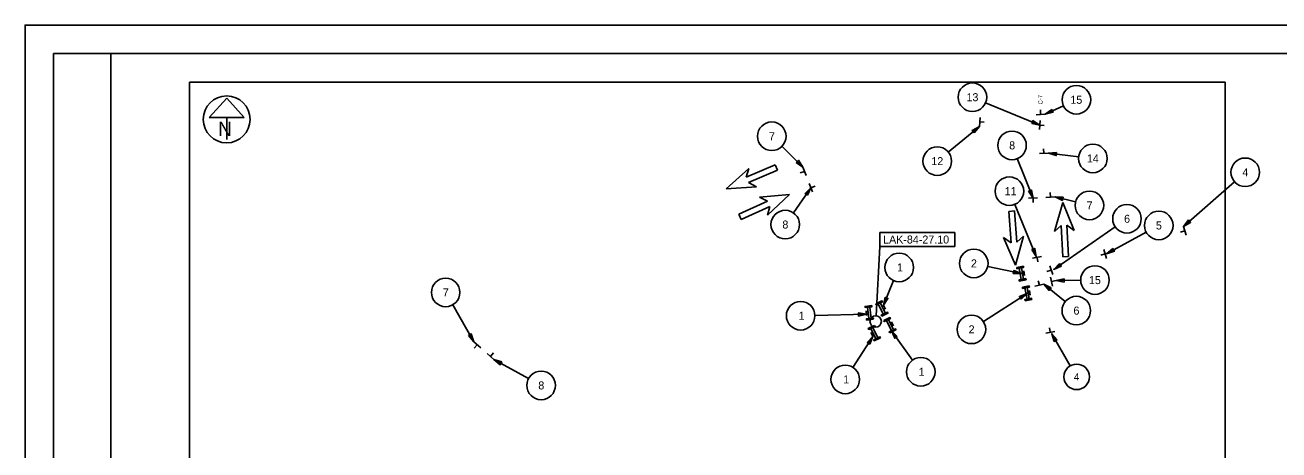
# Model space of a CAD drawing. Extents: x 0 to 54.8, y 0 to 22.
# Drawn here: x 0 to 21.94, y 14.57 to 22 of the extents above; entities that cross this region are included whole.
import ezdxf

# ---------------------------------------------------------------- set-up
doc = ezdxf.new("R2010")
doc.units = 0
for name, color, linetype in [('GM_P_County_Alignment', 7, 'Continuous'), ('GM_X_County', 7, 'Continuous'), ('GM_X_Minor_Lake', 7, 'Continuous'), ('GM_X_Minor_Lake_Text', 7, 'Continuous'), ('GM_X_Minor_River_Text', 7, 'Continuous'), ('GM_X_Township', 7, 'Continuous'), ('GM_X_Township_Road', 7, 'Continuous'), ('GM_X_Township_Road_Text', 7, 'Continuous')]:
    doc.layers.add(name, color=color, linetype=linetype)

msp = doc.modelspace()

# ---------------------------------------------------------------- linework, layer by layer
at = {"layer": 'GM_X_County'}
msp.add_lwpolyline([(0, 0), (34, 0), (34, 22), (0, 22)], close=True, dxfattribs=at)
at = {"layer": 'GM_X_Minor_Lake'}
for p, q in [((3.528, 20.724), (3.22, 20.383)), ((3.836, 20.383), (3.528, 20.724)), ((3.22, 20.383), (3.836, 20.383)), ((3.528, 20.383), (3.528, 19.996)), ((14.891, 16.914), (14.96, 18.128))]:
    msp.add_line(p, q, dxfattribs=at)
for points in [[(21, 21), (21, 11.75), (15, 11.75), (15, 8.743), (2.878, 8.743), (2.878, 21)], [(14.96, 18.368), (14.96, 18.128), (16.268, 18.128), (16.268, 18.368)]]:
    msp.add_lwpolyline(points, close=True, dxfattribs=at)
for centre, radius in [((3.528, 20.35), 0.41), ((14.885, 16.815), 0.1)]:
    msp.add_circle(centre, radius, dxfattribs=at)
at = {"layer": 'GM_X_Minor_Lake_Text'}
for p, q in [((12.619, 19.339), (13.125, 19.552)), ((13.125, 19.552), (13.164, 19.46)), ((12.269, 19.137), (12.663, 19.491)), ((12.663, 19.491), (12.619, 19.339)), ((13.164, 19.46), (12.657, 19.246)), ((13.145, 19.506), (13.145, 19.506)), ((12.798, 19.171), (12.269, 19.137)), ((12.269, 19.137), (12.269, 19.137)), ((12.657, 19.246), (12.798, 19.171)), ((12.492, 18.692), (12.994, 18.917)), ((12.852, 18.989), (13.379, 19.035)), ((12.994, 18.917), (12.852, 18.989)), ((13.379, 19.035), (12.994, 18.672)), ((13.379, 19.035), (13.379, 19.035)), ((18.012, 18.386), (18.16, 18.894)), ((18.16, 18.894), (18.16, 18.894)), ((18.16, 18.894), (18.359, 18.403)), ((12.533, 18.601), (12.492, 18.692)), ((13.035, 18.826), (12.533, 18.601)), ((12.994, 18.672), (13.035, 18.826)), ((17.214, 18.741), (17.314, 18.748)), ((17.254, 18.192), (17.214, 18.741)), ((17.264, 18.744), (17.264, 18.744)), ((17.314, 18.748), (17.354, 18.2)), ((12.512, 18.646), (12.512, 18.646)), ((18.13, 18.492), (18.012, 18.386)), ((18.158, 17.943), (18.13, 18.492)), ((18.359, 18.403), (18.23, 18.497)), ((18.23, 18.497), (18.258, 17.948)), ((17.333, 17.797), (17.124, 18.283)), ((17.124, 18.283), (17.254, 18.192)), ((17.47, 18.308), (17.333, 17.797)), ((17.354, 18.2), (17.47, 18.308)), ((17.333, 17.797), (17.333, 17.797)), ((18.258, 17.948), (18.158, 17.943)), ((18.208, 17.945), (18.208, 17.945)), ((17.433, 17.549), (17.395, 17.745)), ((17.434, 17.651), (17.434, 17.651)), ((17.473, 17.556), (17.435, 17.753)), ((17.45, 17.674), (17.479, 17.68)), ((17.457, 17.635), (17.487, 17.641)), ((17.475, 17.699), (17.491, 17.621)), ((17.533, 17.204), (17.495, 17.4)), ((17.573, 17.211), (17.535, 17.408)), ((17.55, 17.329), (17.579, 17.335)), ((17.576, 17.354), (17.591, 17.276)), ((15.018, 16.942), (14.93, 17.122)), ((15.054, 16.96), (14.966, 17.14)), ((17.534, 17.306), (17.534, 17.306)), ((17.558, 17.29), (17.587, 17.295)), ((14.727, 16.92), (14.718, 16.999)), ((14.75, 16.983), (14.72, 16.98)), ((14.755, 16.943), (14.725, 16.94)), ((14.741, 17.062), (14.764, 16.864)), ((14.772, 16.965), (14.772, 16.965)), ((14.781, 17.067), (14.804, 16.868)), ((14.992, 17.041), (14.992, 17.041)), ((15.001, 17.068), (15.028, 17.081)), ((15.019, 17.032), (15.046, 17.045)), ((15.02, 17.099), (15.054, 17.027)), ((14.801, 16.691), (14.888, 16.511)), ((14.837, 16.708), (14.924, 16.528)), ((15.159, 16.651), (15.072, 16.831)), ((15.195, 16.668), (15.108, 16.848)), ((15.133, 16.749), (15.133, 16.749)), ((15.143, 16.776), (15.17, 16.789)), ((15.16, 16.74), (15.187, 16.753)), ((15.161, 16.807), (15.196, 16.735)), ((14.835, 16.552), (14.8, 16.624)), ((14.836, 16.619), (14.809, 16.606)), ((14.853, 16.583), (14.826, 16.57)), ((14.863, 16.61), (14.863, 16.61))]:
    msp.add_line(p, q, dxfattribs=at)
for points in [[(17.352, 17.757), (17.47, 17.78), (17.474, 17.76), (17.356, 17.737)], [(17.398, 17.521), (17.516, 17.544), (17.512, 17.564), (17.394, 17.541)], [(17.452, 17.412), (17.57, 17.435), (17.574, 17.415), (17.456, 17.392)], [(14.886, 17.123), (14.994, 17.175), (15.002, 17.157), (14.894, 17.105)], [(17.498, 17.176), (17.616, 17.199), (17.612, 17.219), (17.494, 17.196)], [(14.818, 17.092), (14.699, 17.078), (14.701, 17.058), (14.82, 17.072)], [(14.99, 16.907), (15.098, 16.959), (15.09, 16.977), (14.982, 16.925)], [(14.846, 16.853), (14.727, 16.839), (14.724, 16.859), (14.843, 16.873)], [(14.864, 16.744), (14.756, 16.692), (14.765, 16.674), (14.873, 16.726)], [(15.027, 16.831), (15.135, 16.883), (15.144, 16.865), (15.036, 16.813)], [(15.132, 16.615), (15.24, 16.668), (15.231, 16.686), (15.123, 16.633)], [(14.969, 16.528), (14.861, 16.476), (14.852, 16.494), (14.96, 16.546)]]:
    msp.add_lwpolyline(points, close=True, dxfattribs=at)
at = {"layer": 'GM_X_Minor_River_Text'}
for p, q in [((17.851, 20.44), (17.691, 20.431)), ((17.771, 20.436), (17.767, 20.516)), ((16.699, 20.225), (16.711, 20.385)), ((16.705, 20.305), (16.785, 20.299)), ((17.75, 20.171), (17.761, 20.331)), ((17.755, 20.251), (17.835, 20.245)), ((17.908, 19.761), (17.749, 19.752)), ((17.829, 19.757), (17.824, 19.836)), ((13.64, 19.441), (13.566, 19.412)), ((13.612, 19.516), (13.669, 19.367)), ((13.781, 19.08), (13.723, 19.229)), ((13.752, 19.154), (13.826, 19.183)), ((17.558, 18.969), (17.718, 18.977)), ((17.638, 18.973), (17.642, 18.893)), ((18.025, 18.994), (17.865, 18.985)), ((17.945, 18.989), (17.941, 19.069)), ((20.27, 18.477), (20.317, 18.324)), ((20.294, 18.4), (20.217, 18.377)), ((18.901, 17.995), (18.825, 17.972)), ((18.878, 18.071), (18.925, 17.918)), ((17.631, 17.919), (17.789, 17.95)), ((17.71, 17.935), (17.725, 17.856)), ((17.935, 17.789), (17.982, 17.636)), ((17.958, 17.712), (17.882, 17.689)), ((17.981, 17.433), (17.946, 17.589)), ((17.828, 17.468), (17.672, 17.431)), ((17.75, 17.45), (17.731, 17.527)), ((17.964, 17.511), (18.042, 17.529)), ((17.939, 16.625), (17.925, 16.704)), ((7.854, 16.46), (7.974, 16.354)), ((18.018, 16.64), (17.861, 16.611)), ((7.914, 16.407), (7.861, 16.347)), ((8.205, 16.151), (8.085, 16.256)), ((8.145, 16.203), (8.198, 16.264))]:
    msp.add_line(p, q, dxfattribs=at)
at = {"layer": 'GM_X_Township'}
for points in [[(0.5, 21.5), (1.5, 21.5), (1.5, 0.5), (0.5, 0.5)], [(1.5, 21.5), (33.5, 21.5), (33.5, 0.5), (1.5, 0.5)]]:
    msp.add_lwpolyline(points, close=True, dxfattribs=at)
at = {"layer": 'GM_X_Township_Road'}
for p, q in [((16.809, 20.642), (17.755, 20.251)), ((18.17, 20.588), (17.851, 20.44)), ((16.155, 19.777), (16.699, 20.225)), ((13.245, 19.879), (13.612, 19.516)), ((18.437, 19.696), (17.908, 19.761)), ((17.363, 19.663), (17.638, 18.973)), ((13.445, 18.715), (13.752, 19.154)), ((21.163, 19.259), (20.27, 18.477)), ((18.383, 18.905), (18.025, 18.994)), ((17.32, 18.863), (17.696, 17.953)), ((19.076, 18.469), (18.001, 17.725)), ((19.619, 18.375), (18.925, 18)), ((16.846, 17.778), (17.434, 17.651)), ((15.199, 17.529), (15.02, 17.099)), ((18.203, 17.162), (17.828, 17.468)), ((18.472, 17.535), (18.042, 17.529)), ((16.771, 16.811), (17.534, 17.306)), ((7.484, 17.105), (7.854, 16.46)), ((13.822, 16.919), (14.725, 16.94)), ((14.487, 16.01), (14.835, 16.552)), ((15.528, 16.136), (15.159, 16.651)), ((18.29, 16.038), (17.965, 16.599)), ((8.812, 15.816), (8.205, 16.151))]:
    msp.add_line(p, q, dxfattribs=at)
for points in [[(17.966, 20.524), (17.99, 20.474), (17.851, 20.44)], [(16.609, 20.115), (16.574, 20.158), (16.699, 20.225)], [(17.615, 20.279), (17.637, 20.33), (17.755, 20.251)], [(18.051, 19.772), (18.044, 19.716), (17.908, 19.761)], [(13.492, 19.594), (13.532, 19.634), (13.612, 19.516)], [(13.694, 19.024), (13.649, 19.056), (13.752, 19.154)], [(17.56, 19.093), (17.612, 19.113), (17.638, 18.973)], [(18.168, 18.987), (18.154, 18.933), (18.025, 18.994)], [(20.357, 18.59), (20.394, 18.548), (20.27, 18.477)], [(17.617, 18.072), (17.668, 18.093), (17.696, 17.953)], [(19.035, 18.091), (19.062, 18.042), (18.925, 18)], [(18.1, 17.828), (18.132, 17.782), (18.001, 17.725)], [(17.291, 17.653), (17.303, 17.708), (17.434, 17.651)], [(18.181, 17.559), (18.182, 17.503), (18.042, 17.529)], [(17.954, 17.401), (17.918, 17.358), (17.828, 17.468)], [(15.048, 17.239), (15.099, 17.217), (15.02, 17.099)], [(17.432, 17.206), (17.401, 17.253), (17.534, 17.306)], [(14.586, 16.909), (14.584, 16.965), (14.725, 16.94)], [(7.76, 16.567), (7.809, 16.595), (7.854, 16.46)], [(14.783, 16.419), (14.736, 16.449), (14.835, 16.552)], [(15.263, 16.553), (15.218, 16.521), (15.159, 16.651)], [(18.06, 16.492), (18.011, 16.464), (17.965, 16.599)], [(8.341, 16.108), (8.314, 16.058), (8.205, 16.151)]]:
    msp.add_lwpolyline(points, close=True, dxfattribs=at)
for centre, radius in [((16.578, 20.738), 0.25), ((18.397, 20.693), 0.25), ((13.067, 20.055), 0.25), ((17.271, 19.895), 0.25), ((15.962, 19.619), 0.25), ((18.685, 19.666), 0.25), ((21.351, 19.424), 0.25), ((17.225, 19.094), 0.25), ((18.626, 18.845), 0.25), ((13.302, 18.51), 0.25), ((19.282, 18.611), 0.25), ((19.839, 18.494), 0.25), ((15.296, 17.759), 0.25), ((16.602, 17.83), 0.25), ((18.722, 17.538), 0.25), ((7.36, 17.322), 0.25), ((13.572, 16.914), 0.25), ((18.396, 17.004), 0.25), ((16.561, 16.676), 0.25), ((14.352, 15.8), 0.25), ((15.674, 15.933), 0.25), ((18.402, 15.845), 0.223), ((9.031, 15.695), 0.25)]:
    msp.add_circle(centre, radius, dxfattribs=at)
at = {"layer": 'GM_X_Township_Road_Text'}
msp.add_circle((3.528, 20.35), 0.41, dxfattribs=at)

# ---------------------------------------------------------------- texts
at = {"layer": 'GM_P_County_Alignment'}
msp.add_text('C-7', height=0.075, rotation=91.3758, dxfattribs=at).set_placement((17.807, 20.612))
at = {"layer": 'GM_X_Minor_Lake'}
for s, height, p in [('N', 0.25, (3.377, 20.059)), ('LAK-84-27.10', 0.14, (15.015, 18.178))]:
    msp.add_text(s, height=height, dxfattribs=at).set_placement(p)
at = {"layer": 'GM_X_Township_Road'}
for s, height, p in [('13', 0.14, (16.474, 20.668)), ('15', 0.14, (18.292, 20.623)), ('7', 0.14, (13.017, 19.985)), ('8', 0.14, (17.221, 19.825)), ('12', 0.14, (15.859, 19.549)), ('14', 0.14, (18.581, 19.596)), ('4', 0.14, (21.302, 19.354)), ('11', 0.14, (17.142, 19.024)), ('7', 0.14, (18.576, 18.775)), ('6', 0.14, (19.232, 18.541)), ('8', 0.14, (13.252, 18.44)), ('5', 0.14, (19.788, 18.424)), ('1', 0.14, (15.259, 17.689)), ('2', 0.14, (16.552, 17.76)), ('15', 0.14, (18.617, 17.468)), ('7', 0.14, (7.31, 17.252)), ('1', 0.14, (13.535, 16.844)), ('6', 0.14, (18.346, 16.934)), ('2', 0.14, (16.511, 16.606)), ('1', 0.14, (14.316, 15.73)), ('1', 0.14, (15.637, 15.863)), ('4', 0.125, (18.354, 15.782)), ('8', 0.14, (8.981, 15.625))]:
    msp.add_text(s, height=height, dxfattribs=at).set_placement(p)

doc.saveas('drawing.dxf')
